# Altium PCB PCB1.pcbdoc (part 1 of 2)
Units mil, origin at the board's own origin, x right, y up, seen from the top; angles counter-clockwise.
Board outline 2401.6 x 2401.6 mil, 2 copper layers (Top Layer, Bottom Layer), stack 62.2 mil thick; 60 components, 46 nets, 313 pads, 160 vias.
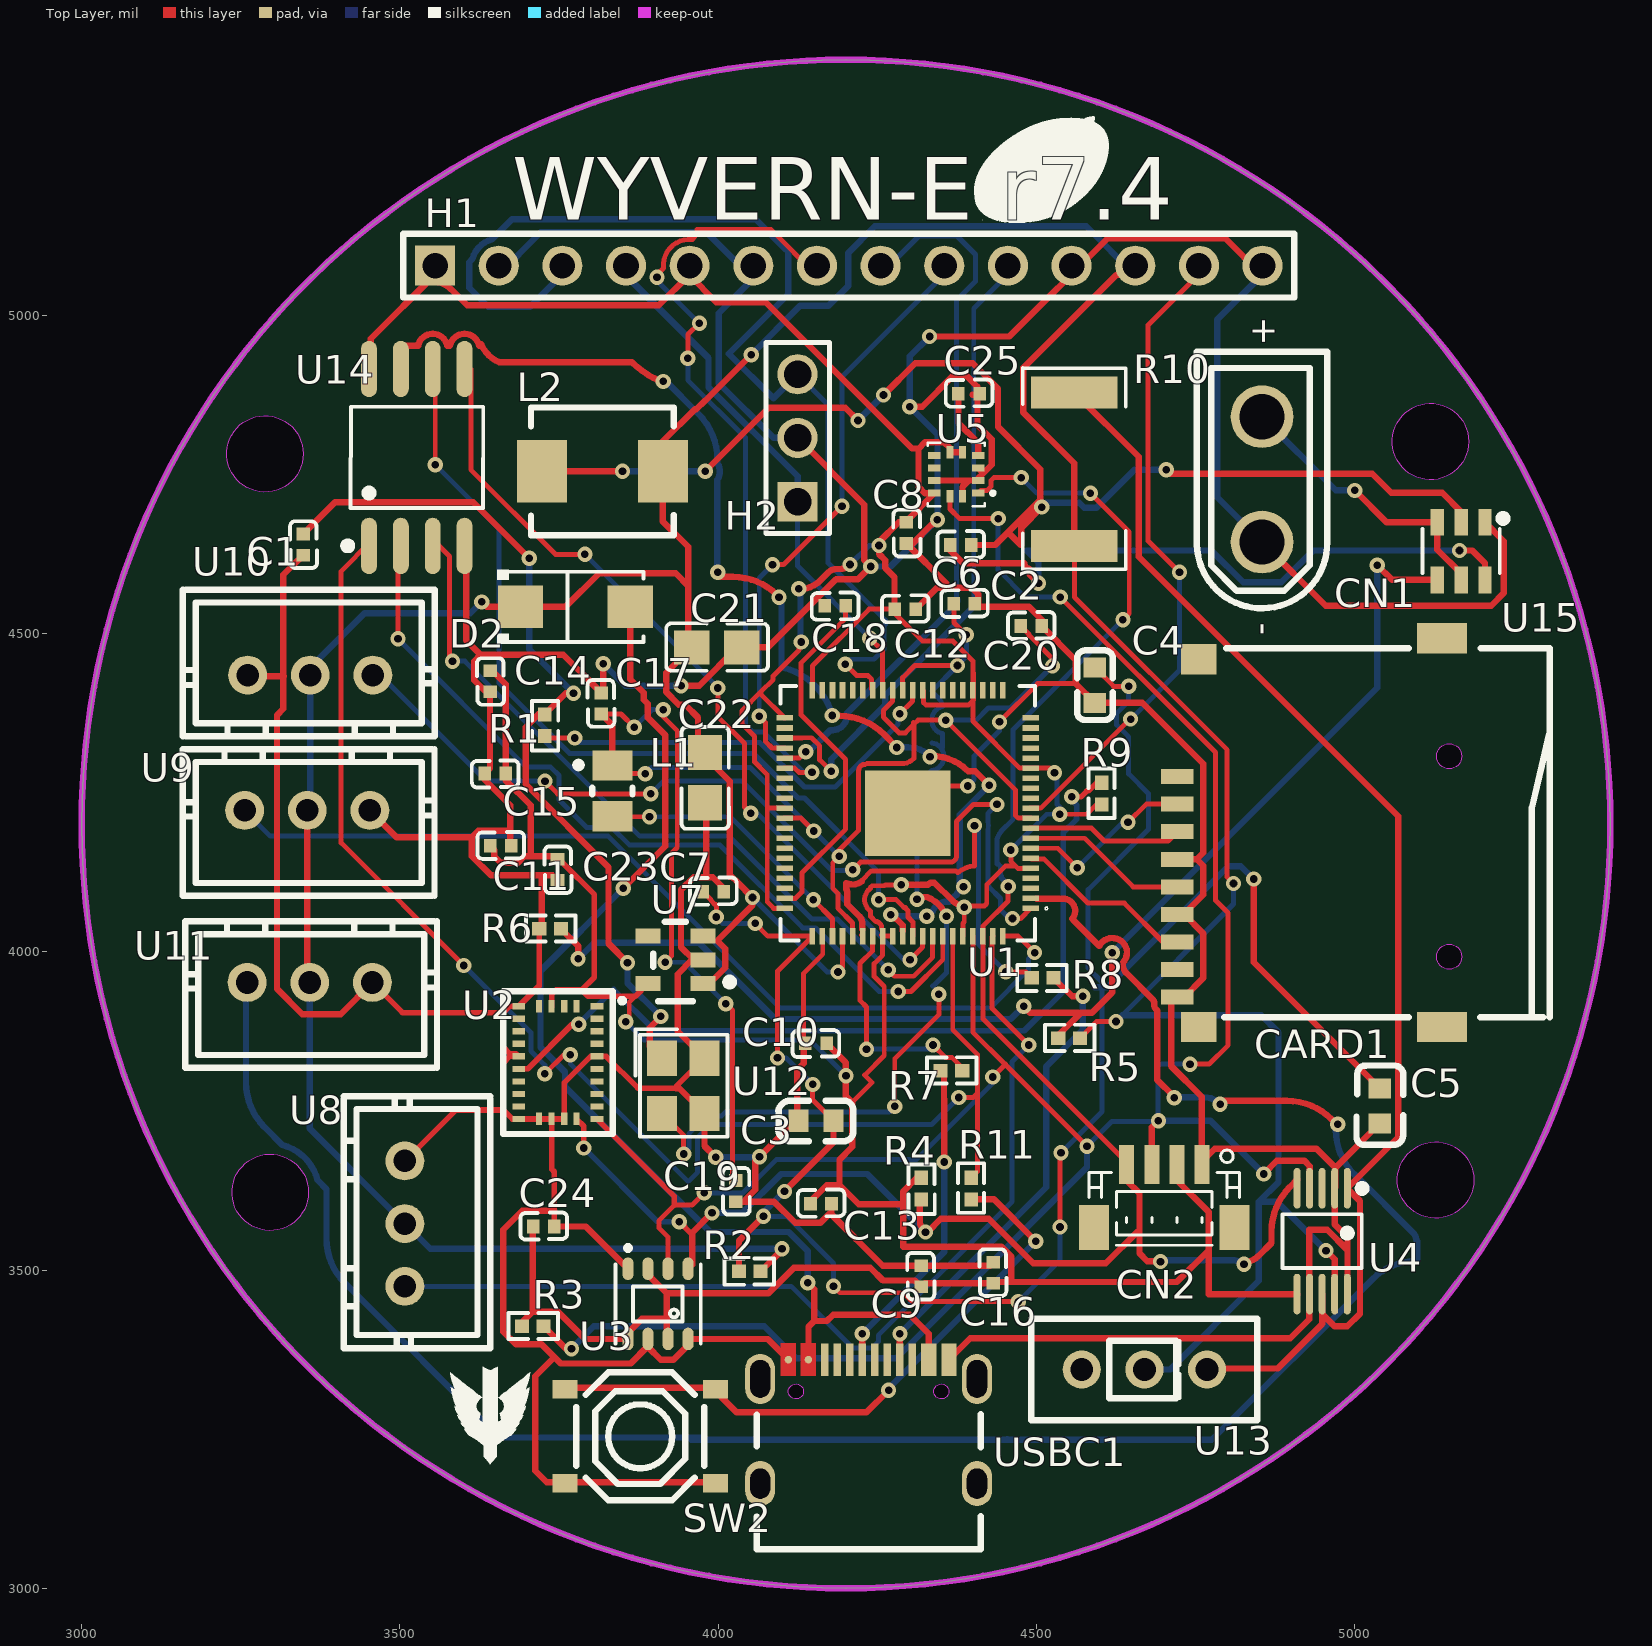
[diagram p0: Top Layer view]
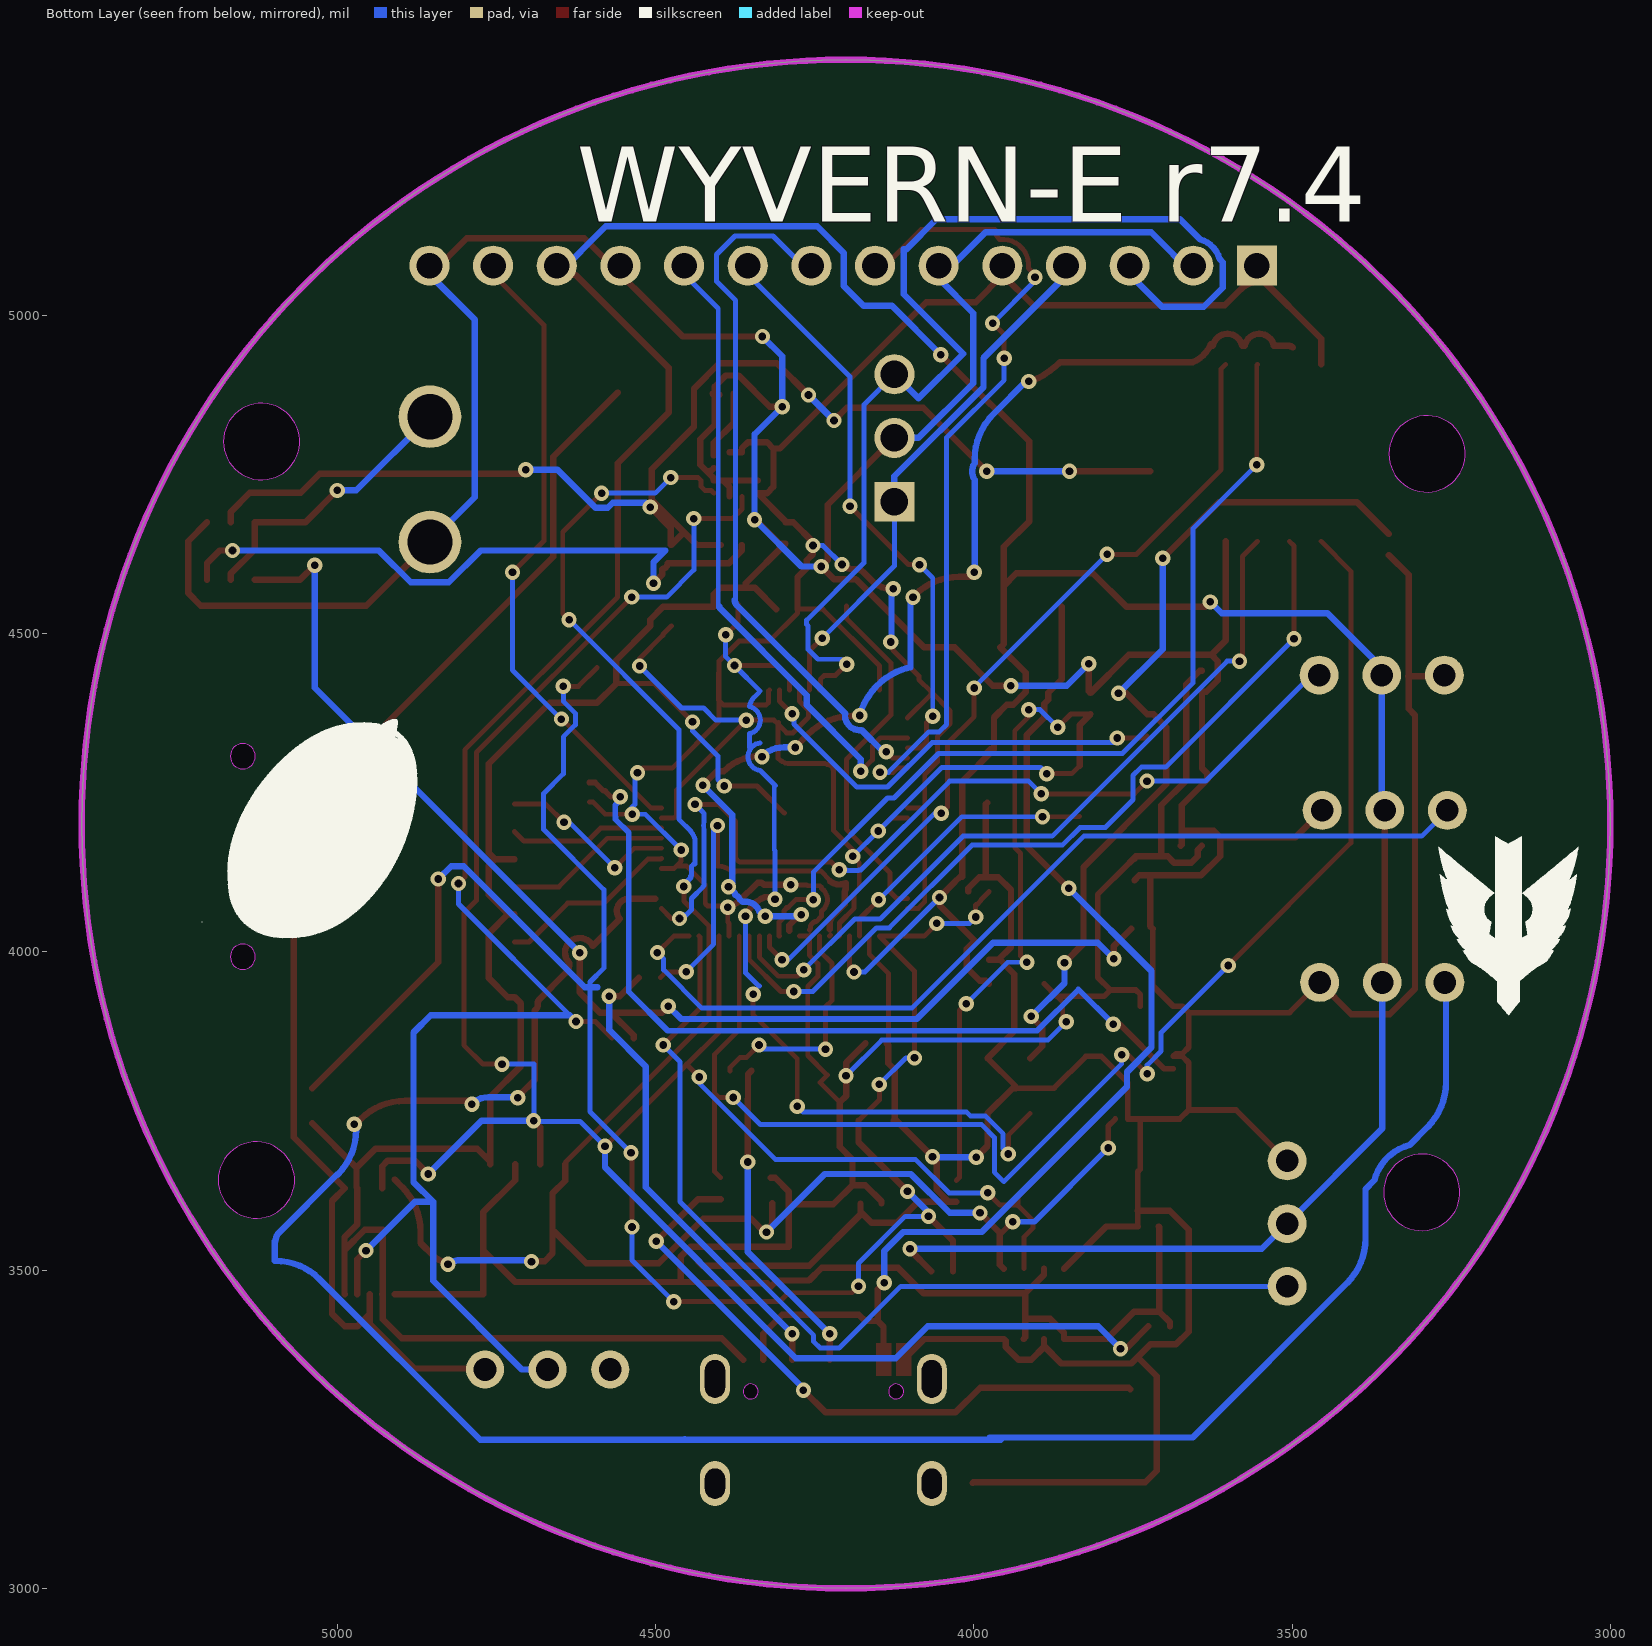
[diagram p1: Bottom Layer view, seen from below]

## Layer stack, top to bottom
Top Solder Mask Layer: solder mask 0.4, Dk 3.3
Top Layer: signal copper 1.4
Dielectric1: surface 59.4, FR4, Dk 4.5
Bottom Layer: signal copper 1.4
Bottom Solder Mask Layer: solder mask 0.4, Dk 3.3

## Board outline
5401.6,4200.8 ccw(c4200.8,4200.8) 3000,4200.8 ccw(c4200.8,4200.8)
cut-out: 3348,4782.3 3347.6,4775.5 3346.5,4768.7 3344.5,4762.1 3341.9,4755.8 3338.5,4749.8 3334.5,4744.3 3329.8,4739.3 3324.7,4734.8 3319,4730.9 3312.9,4727.7 3306.5,4725.2 3299.9,4723.5 3293.1,4722.5 3286.3,4722.3 3279.4,4722.9 3272.7,4724.2 3266.2,4726.4 3260,4729.2 3254.1,4732.7 3248.7,4736.9 3243.8,4741.7 3239.4,4747 3235.7,4752.8 3232.7,4758.9 3230.4,4765.4 3228.8,4772.1 3228,4778.9 3228,4785.7 3228.8,4792.5 3230.4,4799.2 3232.7,4805.7 3235.7,4811.8 3239.4,4817.6 3243.8,4822.9 3248.7,4827.7 3254.1,4831.9 3260,4835.4 3266.2,4838.3 3272.7,4840.4 3279.4,4841.7 3286.3,4842.3 3293.1,4842.1 3299.9,4841.2 3306.5,4839.4 3312.9,4836.9 3319,4833.7 3324.7,4829.9 3329.8,4825.4 3334.5,4820.3 3338.5,4814.8 3341.9,4808.8 3344.5,4802.5 3346.5,4795.9 3347.6,4789.2
cut-out: 5179,4801.7 5178.6,4794.8 5177.4,4788.1 5175.5,4781.5 5172.8,4775.2 5169.4,4769.2 5165.4,4763.7 5160.8,4758.6 5155.6,4754.1 5149.9,4750.2 5143.9,4747 5137.5,4744.6 5130.9,4742.8 5124.1,4741.8 5117.2,4741.6 5110.4,4742.2 5103.7,4743.6 5097.2,4745.7 5090.9,4748.6 5085,4752.1 5079.6,4756.3 5074.7,4761.1 5070.4,4766.4 5066.7,4772.1 5063.6,4778.3 5061.3,4784.7 5059.8,4791.4 5059,4798.2 5059,4805.1 5059.8,4811.9 5061.3,4818.6 5063.6,4825 5066.7,4831.2 5070.4,4837 5074.7,4842.3 5079.6,4847 5085,4851.2 5090.9,4854.8 5097.2,4857.6 5103.7,4859.7 5110.4,4861.1 5117.2,4861.7 5124.1,4861.5 5130.9,4860.5 5137.5,4858.8 5143.9,4856.3 5149.9,4853.1 5155.6,4849.2 5160.8,4844.7 5165.4,4839.7 5169.4,4834.1 5172.8,4828.2 5175.5,4821.8 5177.4,4815.3 5178.6,4808.5
cut-out: 3356.3,3622.1 3355.9,3615.3 3354.7,3608.5 3352.8,3601.9 3350.1,3595.6 3346.7,3589.7 3342.7,3584.1 3338.1,3579.1 3332.9,3574.6 3327.2,3570.7 3321.2,3567.5 3314.8,3565 3308.1,3563.3 3301.4,3562.3 3294.5,3562.1 3287.7,3562.7 3281,3564.1 3274.4,3566.2 3268.2,3569 3262.3,3572.6 3256.9,3576.7 3252,3581.5 3247.6,3586.8 3243.9,3592.6 3240.9,3598.7 3238.6,3605.2 3237.1,3611.9 3236.3,3618.7 3236.3,3625.5 3237.1,3632.4 3238.6,3639 3240.9,3645.5 3243.9,3651.6 3247.6,3657.4 3252,3662.7 3256.9,3667.5 3262.3,3671.7 3268.2,3675.2 3274.4,3678.1 3281,3680.2 3287.7,3681.6 3294.5,3682.1 3301.4,3681.9 3308.1,3681 3314.8,3679.2 3321.2,3676.7 3327.2,3673.5 3332.9,3669.7 3338.1,3665.2 3342.7,3660.1 3346.7,3654.6 3350.1,3648.6 3352.8,3642.3 3354.7,3635.7 3355.9,3629
cut-out: 5187.2,3641.5 5186.8,3634.6 5185.6,3627.9 5183.7,3621.3 5181,3615 5177.7,3609 5173.6,3603.5 5169,3598.4 5163.8,3593.9 5158.2,3590.1 5152.1,3586.9 5145.7,3584.4 5139.1,3582.6 5132.3,3581.6 5125.4,3581.5 5118.6,3582 5111.9,3583.4 5105.4,3585.5 5099.1,3588.4 5093.3,3591.9 5087.8,3596.1 5082.9,3600.9 5078.6,3606.2 5074.9,3611.9 5071.9,3618.1 5069.6,3624.6 5068,3631.2 5067.2,3638 5067.2,3644.9 5068,3651.7 5069.6,3658.4 5071.9,3664.8 5074.9,3671 5078.6,3676.8 5082.9,3682.1 5087.8,3686.8 5093.3,3691 5099.1,3694.6 5105.4,3697.4 5111.9,3699.5 5118.6,3700.9 5125.4,3701.5 5132.3,3701.3 5139.1,3700.3 5145.7,3698.6 5152.1,3696.1 5158.2,3692.9 5163.8,3689 5169,3684.5 5173.6,3679.5 5177.7,3673.9 5181,3668 5183.7,3661.6 5185.6,3655.1 5186.8,3648.3

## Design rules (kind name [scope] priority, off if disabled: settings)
BoardOutlineClearance safeClearance [All] p0: genericclearance=10 ignorepadtopadclearanceinfootprint=FALSE except(0: Arc-SplitContinuation Track-SplitContinuation SMDPad-SplitContinuation THPad-SplitContinuation Via-SplitContinuation Fill-SplitContinuation Poly-SplitContinuation Region-SplitContinuation Text-SplitContinuation)
BoardOutlineClearance otherClearance [All] p0: genericclearance=10 ignorepadtopadclearanceinfootprint=FALSE except(0: Arc-SplitContinuation Track-SplitContinuation SMDPad-SplitContinuation THPad-SplitContinuation Via-SplitContinuation Fill-SplitContinuation Poly-SplitContinuation Region-SplitContinuation Text-SplitContinuation)
Clearance safeClearance [All] p1: gap=7 ignorepadtopadclearanceinfootprint=FALSE
Clearance otherClearance [All] p1: gap=7 ignorepadtopadclearanceinfootprint=FALSE
DiffPairsRouting differentialPair [All] p1: maxuncoupledlength=10 minlimit=6 maxlimit=Infinity mostfreqgap=6 toplayer_minwidth=5 toplayer_prefwidth=10 toplayer_maxwidth=100 bottomlayer_minwidth=5 bottomlayer_prefwidth=10 bottomlayer_maxwidth=100
PasteMaskExpansion pasteMaskExpansion [All] p1: expansion=0
PlaneConnect innerPlane [All] p1: planeconnectstyle=Relief reliefexpansion=20 reliefentries=4 reliefconductorwidth=10 reliefairgap=10
PolygonConnect copperRegion [All] p1: connectstyle=Relief reliefentries=4 reliefconductorwidth=10 polygonreliefangle="90 Angle" airgapwidth=10
RoutingVias viaSize [All] p1: viastyle="Through Hole" holewidth=12.0078 minholewidth=11.811 maxholewidth=236.2204 width=12.0078 minwidth=11.811 maxwidth=236.2204
SolderMaskExpansion solderMaskExpansion [IsVia] p1: useseparateexpansions=TRUE expansion=-1000 expansionbottom=-1000
SolderMaskExpansion solderMaskExpansion [All] p2: useseparateexpansions=TRUE expansion=0.9843 expansionbottom=2.0079
Width trackWidth [All] p1: maxlimit=100 minlimit=5 preferedwidth=10

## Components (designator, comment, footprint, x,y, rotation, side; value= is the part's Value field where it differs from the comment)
C1 "15pF" C0402#1 3347.9,4639.8 r270 top
C2 "15pF" C0402#1 4386.9,4546.8 r0 top
C3 "4.7uF" C0603#1 4153.6,3734.4 r180 top
C4 "4.7uF" C0603#2 4591.9,4418.8 r270 top
C5 "4.7uF" C0603#2 5039.4,3758 r270 top
C6 "100nF" C0402#2 4380.8,4639.1 r0 top
C7 "100nF" C0402#2 3992.3,4094.7 r0 top
C8 "100nF" C0402#2 4295.8,4658.1 r270 top
C9 "100nF" C0402#1 4319,3490.3 r90 top
C10 "100nF" C0402#1 4153.6,3856.4 r180 top
C11 "100nF" C0402#2 3658.2,4166.5 r0 top
C12 "100nF" C0402#1 4293.7,4538.4 r0 top
C13 "100nF" C0402#3 4161.5,3604.4 r0 top
C14 "100nF" C0402#2 3641.6,4424.9 r270 top
C15 "100nF" C0402#2 3649.7,4280.1 r180 top
C16 "100nF" C0402#1 4432.4,3495.9 r90 top
C17 "100nF" C0402#3 3816.6,4390.1 r90 top
C18 "100nF" C0402#1 4183.7,4543.7 r180 top
C19 "100nF" C0402#1 4027.6,3624.1 r270 top
C20 "100nF" C0402#2 4491.7,4511.9 r0 top
C21 "22uF" C0805#1 3997.7,4478.2 r0 top
C22 "22uF" C0805#2 3979.1,4273.8 r270 top
C23 "100nF" C0402#2 3747.6,4129 r270 top
C24 "100nF" C0402#2 3725.8,3568.5 r0 top
C25 "100nF" C0402#1 4394.1,4877 r0 top
CARD1 "TF-01A" TF-SMD_TF-01A 4929.2,4187.1 r90 top
CN1 "XT30UPB-M" CONN-TH_XT30UPB-M 4854.4,4742.2 r90 top
CN2 "BM04B-SRSS-TB(LF)(SN)" CONN-SMD_BM04B-SRSS-TB 4700.9,3616.3 r180 top
D2 "SS14" SMA_L4.4-W2.6-LS5.0-RD 3775.5,4541.9 r0 top
H1 "2011-1X14G00SB" HDR-TH_14P-P2.54-V-M_4 4205.2,5078 r0 top
H2 "2.54-1*3P针" HDR-TH_3P-P2.54-V-M-1 4124.8,4807.4 r90 top
L1 "3.3uH" IND-SMD_L2.0-W1.6_AOTA-B201610S3R3-101-T 3833.8,4253 r90 top
L2 "2.2uH" IND-SMD_L5.7-W5.1 3818.1,4754.8 r0 top
R1 "1kΩ" R0402#1 3727.6,4356 r90 top
R2 "33Ω" R0402#1 4049.7,3498.2 r0 top
R3 "10kΩ" R0402#1 3708.7,3411.5 r180 top
R4 "10kΩ" R0402#1 4319,3628.1 r90 top
R5 "56kΩ" R0402#2 4551.3,3864.3 r180 top
R6 "10.2kΩ" R0402#1 3735.8,4036.2 r180 top
R7 "27Ω" R0402#1 4366.2,3813.1 r180 top
R8 "27Ω" R0402#2 4509.5,3959.4 r0 top
R9 "10kΩ" R0402#1 4602.7,4248.4 r270 top
R10 "10mΩ" R2512 4559.5,4758.1 r270 top
R11 "1kΩ" R0402#2 4397.7,3628.1 r270 top
SW2 "TS-1187A-B-A-B" SW-SMD_4P-L5.1-W5.1-P3.70-LS6.5-TL_H1.5 3877.5,3238.8 r0 top
U1 "RP2350B" QFN-80_L10.0-W10.0-P0.40-TL-EP3.4 4297.7,4217.8 r180 top
U2 "BNO055" LGA-28_L5.2-W3.8-P0.50-BL 3748.1,3825.9 r180 top
U3 "BME680" LGA-8_L3.0-W3.0-P0.80-TR 3905.6,3447 r90 top
U4 "INA226AIDGSR" MSOP-10_L3.0-W3.0-P0.50-LS5.0-BL 4948.9,3545.4 r180 top
U5 "LIS3MDLTR" LGA-12_L2.0-W2.0-P0.50-BL 4374.1,4750.1 r90 top
U7 "AP2112K-3.3TRG1" SOT-23-5_L2.9-W1.6-P0.95-LS2.8-BR 3932.9,3987.4 r0 top
U8 "B3B-XH-A(LF)(SN)" CONN-TH_3P-P2.50_A2501WV2-3P#1 3507.8,3573 r90 top
U9 "B3B-XH-A(LF)(SN)" CONN-TH_3P-P2.50_A2501WV2-3P#2 3354.4,4222.1 r0 top
U10 "B3B-XH-A(LF)(SN)" CONN-TH_3P-P2.50_A2501WV2-3P#2 3359.1,4434.8 r180 top
U11 "B3B-XH-A(LF)(SN)" CONN-TH_3P-P2.50_A2501WV2-3P#3 3358.3,3951.8 r0 top
U12 "12MHz" CRYSTAL-SMD_4P-L3.2-W2.5-BL 3945,3789.5 r270 top
U13 "SS-12D00-G3" SW-TH_3P-L8.8-W3.9-P2.50_SS12D00G3 4669.6,3343.8 r180 top
U14 "W25Q32JVSSIQ" SOIC-8_L5.3-W5.3-P1.27-LS8.0-BL 3526.5,4776.7 r0 top
U15 "TPS564201DDCR" SOT-23-6_L2.9-W1.6-P0.95-LS2.8-BL 5167.3,4629.6 r180 top
USBC1 "TYPE-C-31-M-12" USB-C_SMD-TYPE-C-31-M-12_1 4236.3,3261.9 r0 top

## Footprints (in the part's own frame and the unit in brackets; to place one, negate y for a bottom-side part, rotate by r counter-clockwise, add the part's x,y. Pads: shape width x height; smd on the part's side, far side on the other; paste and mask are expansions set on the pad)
C0402#1 [mil]
  rect 19.7x21.3 smd paste+0 mask+0: 1(-16.6,0) 2(16.5,0)
  silkscreen extent -36,-21 37,22
C0402#2 [mil]
  rect 19.7x21.3 smd paste+0 mask+0: 1(-16.5,0) 2(16.6,0)
  silkscreen extent -36,-21 37,22
C0402#3 [mil]
  rect 19.7x21.3 smd paste+0 mask+0: 1(-16.5,0) 2(16.5,0)
  silkscreen extent -36,-21 37,22
C0603#1 [mil]
  rect 31.5x35.4 smd: 1(-27.6,0) 2(27.5,0)
  silkscreen extent -59,-32 59,32
C0603#2 [mil]
  rect 31.5x35.4 smd paste+0 mask+0: 1(-27.6,0) 2(27.6,0)
  silkscreen extent -55,-28 55,28
C0805#1 [mil]
  rect 55.5x53.1 smd paste+0 mask+0: 1(-39.4,0) 2(39.4,0)
  silkscreen extent -79,-37 80,38
C0805#2 [mil]
  rect 55.5x53.1 smd paste-3937 mask+2: 1(-39.3,0) 2(39.4,0)
  silkscreen extent -79,-37 81,38
CONN-SMD_BM04B-SRSS-TB [mil]
  rect 47.2x70.9 smd: 0(-110.2,49.7) 0(110.3,49.7)
  rect 23.6x61 smd: 1(-59,-49.7) 2(-19.7,-49.7) 3(19.7,-49.7) 4(59.1,-49.7)
  silkscreen extent -118,-72 118,77
CONN-TH_3P-P2.50_A2501WV2-3P#1 [mil]
  round 61 hole 35.4: 1(-98.5,0) 2(0,0) 3(98.4,0)
  silkscreen extent -196,-134 200,96
CONN-TH_3P-P2.50_A2501WV2-3P#2 [mil]
  round 61 hole 35.4: 1(-98.4,0) 2(0,0) 3(98.4,0)
  silkscreen extent -196,-134 200,96
CONN-TH_3P-P2.50_A2501WV2-3P#3 [mil]
  round 61 hole 35.4: 1(-98.4,0) 2(0.1,0) 3(98.5,0)
  silkscreen extent -196,-134 200,96
CONN-TH_XT30UPB-M [mil]
  round 98.4 hole 70.9: 1(-98.4,0) 2(98.5,0)
  silkscreen extent -202,-102 201,102
CRYSTAL-SMD_4P-L3.2-W2.5-BL [mil]
  rect 55.1x47.2 smd paste+0 mask+0: 1(-43.3,-33.5) 2(43.3,-33.5) 3(43.3,33.4) 4(-43.3,33.4)
  silkscreen extent -89,-75 80,70
HDR-TH_3P-P2.54-V-M-1 [mil]
  rect 62x63 hole 43.3: 1(-100,0)
  round 63 hole 43.3: 2(0,0) 3(100,0)
  silkscreen extent -150,-50 150,50
HDR-TH_14P-P2.54-V-M_4 [mil]
  rect 63x63 hole 40.2: 1(-650,0)
  round 63 hole 40.2: 2(-550,0) 3(-450,0) 4(-350,0) 5(-250,0) 6(-150,0) 7(-50,0) 8(50,0) 9(150,0) 10(250,0) 11(350,0) 12(450,0) 13(550,0) 14(650,0)
  silkscreen extent -700,-50 700,50
IND-SMD_L2.0-W1.6_AOTA-B201610S3R3-101-T [mil]
  rect 47.2x63 smd paste+0 mask+0: 1(-40,0) 2(39.4,0)
  silkscreen extent -6,-32 46,58
IND-SMD_L5.7-W5.1 [mil]
  rect 78.7x98.4 smd paste+0 mask+2: 1(-95,0) 2(95,0)
  silkscreen extent -112,-100 112,100
LGA-8_L3.0-W3.0-P0.80-TR [mil]
  oval 35.4x17.6 smd paste+0 mask+0: 1(55.1,47.2) 2(55.1,15.8) 3(55.1,-15.7) 4(55.1,-47.2) 5(-55.2,-47.2) 6(-55.2,-15.7) 7(-55.2,15.8) 8(-55.2,47.2)
  silkscreen extent -62,-67 92,67
LGA-12_L2.0-W2.0-P0.50-BL [mil]
  rect 11x19.7 smd: 1(-29.5,-34.4) 2(-9.8,-34.4) 3(9.9,-34.4) 4(29.5,-34.4) 7(29.5,34.5) 8(9.9,34.5) 9(-9.8,34.5) 10(-29.5,34.5)
  rect 19.7x11 smd: 5(34.5,-9.8) 6(34.5,9.8) 11(-34.4,9.8) 12(-34.4,-9.8)
  silkscreen extent -50,-60 50,45
LGA-28_L5.2-W3.8-P0.50-BL [mil]
  rect 19.7x9.8 smd: 1(-61.5,-88.6) 6(61.5,-88.6) 7(61.5,-68.9) 8(61.5,-49.2) 9(61.5,-29.6) 10(61.5,-9.9) 11(61.5,9.8) 12(61.5,29.5) 13(61.5,49.2) 14(61.5,68.9) 15(61.5,88.5) 20(-61.5,88.5) 21(-61.5,68.9) 22(-61.5,49.2) 23(-61.5,29.5) 24(-61.5,9.8) 25(-61.5,-9.9) 26(-61.5,-29.6) 27(-61.5,-49.2) 28(-61.5,-68.9)
  rect 9.8x19.7 smd: 2(-29.5,-88.6) 3(-9.9,-88.6) 4(9.8,-88.6) 5(29.5,-88.6) 16(29.5,88.5) 17(9.8,88.5) 18(-9.9,88.5) 19(-29.5,88.5)
  silkscreen extent -105,-112 86,112
MSOP-10_L3.0-W3.0-P0.50-LS5.0-BL [mil]
  oval 11x63.8 smd paste+0 mask+0: 1(-39.4,-83.1) 2(-19.7,-83.1) 3(0,-83.1) 4(19.7,-83.1) 5(39.4,-83.1) 6(39.4,83.1) 7(19.7,83.1) 8(0,83.1) 9(-19.7,83.1) 10(-39.4,83.1)
  silkscreen extent -69,-89 62,42
QFN-80_L10.0-W10.0-P0.40-TL-EP3.4 [mil]
  rect 26.2x8.7 smd: 1(-193.2,149.6) 2(-193.2,133.9) 3(-193.2,118.1) 4(-193.2,102.4) 5(-193.2,86.6) 6(-193.2,70.9) 7(-193.2,55.1) 8(-193.2,39.4) 9(-193.2,23.6) 10(-193.2,7.9) 11(-193.2,-7.8) 12(-193.2,-23.6) 13(-193.2,-39.3) 14(-193.2,-55.1) 15(-193.2,-70.8) 16(-193.2,-86.6) 17(-193.2,-102.3) 18(-193.2,-118.1) 19(-193.2,-133.8) 20(-193.2,-149.6) 41(193.2,-149.6) 42(193.2,-133.8) 43(193.2,-118.1) 44(193.2,-102.3) 45(193.2,-86.6) 46(193.2,-70.8) 47(193.2,-55.1) 48(193.2,-39.3) 49(193.2,-23.6) 50(193.2,-7.8) 51(193.2,7.9) 52(193.2,23.6) 53(193.2,39.4) 54(193.2,55.1) 55(193.2,70.9) 56(193.2,86.6) 57(193.2,102.4) 58(193.2,118.1) 59(193.2,133.9) 60(193.2,149.6)
  rect 8.7x26.2 smd: 21(-149.6,-193.2) 22(-133.8,-193.2) 23(-118.1,-193.2) 24(-102.3,-193.2) 25(-86.6,-193.2) 26(-70.8,-193.2) 27(-55.1,-193.2) 28(-39.3,-193.2) 29(-23.6,-193.2) 30(-7.8,-193.2) 31(7.9,-193.2) 32(23.6,-193.2) 33(39.4,-193.2) 34(55.1,-193.2) 35(70.9,-193.2) 36(86.6,-193.2) 37(102.4,-193.2) 38(118.1,-193.2) 39(133.9,-193.2) 40(149.6,-193.2) 61(149.6,193.2) 62(133.9,193.2) 63(118.1,193.2) 64(102.4,193.2) 65(86.6,193.2) 66(70.9,193.2) 67(55.1,193.2) 68(39.4,193.2) 69(23.6,193.2) 70(7.9,193.2) 71(-7.8,193.2) 72(-23.6,193.2) 73(-39.3,193.2) 74(-55.1,193.2) 75(-70.8,193.2) 76(-86.6,193.2) 77(-102.3,193.2) 78(-118.1,193.2) 79(-133.8,193.2) 80(-149.6,193.2)
  rect 133.9x133.9 smd: 81(0,0)
  silkscreen extent -220,-200 200,200
R0402#1 [mil]
  rect 22.3x21.3 smd paste-3937 mask+0: 1(-17.1,0) 2(17,0)
  silkscreen extent -40,-21 38,20
R0402#2 [mil]
  rect 22.3x21.3 smd paste-3937 mask+0: 1(-17,0) 2(17.1,0)
  silkscreen extent -40,-21 38,20
R2512 [mil]
  rect 50.5x136.1 smd paste-3937 mask+2: 1(-120.7,0) 2(120.8,0)
  silkscreen extent -159,-81 158,81
SMA_L4.4-W2.6-LS5.0-RD [mil]
  rect 70.9x66.9 smd: 1(-86.3,0) 2(86.3,0)
  silkscreen extent -122,-58 107,58
SOIC-8_L5.3-W5.3-P1.27-LS8.0-BL [mil]
  oval 24.8x88.6 smd: 1(-75,-139) 2(-25,-139) 3(25,-139) 4(75,-139) 5(75,139) 6(25,139) 7(-25,139) 8(-75,139)
  silkscreen extent -115,-145 104,80
SOT-23-5_L2.9-W1.6-P0.95-LS2.8-BR [mil]
  rect 39.4x23.6 smd paste+0 mask+2: 1(43.3,-37.4) 2(43.3,0) 3(43.3,37.4) 4(-43.3,37.4) 5(-43.3,-37.4)
  silkscreen extent -35,-65 91,60
SOT-23-6_L2.9-W1.6-P0.95-LS2.8-BL [mil]
  rect 20.9x42.2 smd: 1(-37.4,-45.3) 2(0,-45.3) 3(37.4,-45.3) 4(37.4,45.2) 5(0,45.2) 6(-37.4,45.2)
  silkscreen extent -72,-57 61,35
SW-SMD_4P-L5.1-W5.1-P3.70-LS6.5-TL_H1.5 [mil]
  rect 39.4x29.5 smd: 1(-118.1,73.9) 2(118.1,73.9) 3(-118.1,-73.8) 4(118.1,-73.8)
  silkscreen extent -100,-100 100,100
SW-TH_3P-L8.8-W3.9-P2.50_SS12D00G3 [mil]
  round 60 hole 36 paste+0 mask+2: 1(-98.4,0) 2(0,0) 3(98.4,0)
  silkscreen extent -178,-80 178,80
TF-SMD_TF-01A [mil]
  rect 23.6x51.2 smd: 1(88.2,207.7) 2(44.9,207.7) 3(1.6,207.7) 4(-41.7,207.7) 5(-85,207.7) 6(-128.3,207.7) 7(-171.6,207.7) 8(-214.9,207.7) 9(-258.2,207.7)
  rect 47.2x55.1 smd: 10(-305.5,174.2) 13(272.5,174.2)
  rect 47.2x78.7 smd paste+0 mask+0: 11(-305.5,-207.7) 12(305.5,-207.7)
  Board Outline Layer lines w0.1: -194.9,-199.5 -198.7,-199.8 -202.4,-201 -205.8,-202.8 -208.8,-205.2 -211.2,-208.2 -213,-211.6 -214.2,-215.3 -214.5,-219.1 -214.2,-223 -213,-226.7 -211.2,-230.1 -208.8,-233.1 -205.8,-235.5 -202.4,-237.3 -198.7,-238.5 -194.9,-238.8 -191,-238.5 -187.3,-237.3 -183.9,-235.5 -180.9,-233.1 -178.5,-230.1 -176.7,-226.7 -175.5,-223 -175.2,-219.1 -175.5,-215.3 -176.7,-211.6 -178.5,-208.2 -180.9,-205.2 -183.9,-202.8 -187.3,-201 -191,-199.8 -194.9,-199.5 ; 120.1,-199.5 116.3,-199.8 112.6,-201 109.2,-202.8 106.2,-205.2 103.7,-208.2 101.9,-211.6 100.8,-215.3 100.4,-219.1 100.8,-223 101.9,-226.7 103.7,-230.1 106.2,-233.1 109.2,-235.5 112.6,-237.3 116.3,-238.5 120.1,-238.8 123.9,-238.5 127.6,-237.3 131,-235.5 134,-233.1 136.5,-230.1 138.3,-226.7 139.4,-223 139.8,-219.1 139.4,-215.3 138.3,-211.6 136.5,-208.2 134,-205.2 131,-202.8 127.6,-201 123.9,-199.8 120.1,-199.5
  Board Outline Layer region: -175.2,-219.1 -175.5,-223 -176.7,-226.7 -178.5,-230.1 -180.9,-233.1 -183.9,-235.5 -187.3,-237.3 -191,-238.5 -194.9,-238.8 -198.7,-238.5 -202.4,-237.3 -205.8,-235.5 -208.8,-233.1 -211.2,-230.1 -213,-226.7 -214.2,-223 -214.5,-219.1 -214.2,-215.3 -213,-211.6 -211.2,-208.2 -208.8,-205.2 -205.8,-202.8 -202.4,-201 -198.7,-199.8 -194.9,-199.5 -191,-199.8 -187.3,-201 -183.9,-202.8 -180.9,-205.2 -178.5,-208.2 -176.7,-211.6 -175.5,-215.3
  Board Outline Layer region: -175.2,-219.1 -175.5,-223 -176.7,-226.7 -178.5,-230.1 -180.9,-233.1 -183.9,-235.5 -187.3,-237.3 -191,-238.5 -194.9,-238.8 -198.7,-238.5 -202.4,-237.3 -205.8,-235.5 -208.8,-233.1 -211.2,-230.1 -213,-226.7 -214.2,-223 -214.5,-219.1 -214.2,-215.3 -213,-211.6 -211.2,-208.2 -208.8,-205.2 -205.8,-202.8 -202.4,-201 -198.7,-199.8 -194.9,-199.5 -191,-199.8 -187.3,-201 -183.9,-202.8 -180.9,-205.2 -178.5,-208.2 -176.7,-211.6 -175.5,-215.3
  Board Outline Layer region: 139.8,-219.1 139.4,-223 138.3,-226.7 136.5,-230.1 134,-233.1 131,-235.5 127.6,-237.3 123.9,-238.5 120.1,-238.8 116.3,-238.5 112.6,-237.3 109.2,-235.5 106.2,-233.1 103.7,-230.1 101.9,-226.7 100.8,-223 100.4,-219.1 100.8,-215.3 101.9,-211.6 103.7,-208.2 106.2,-205.2 109.2,-202.8 112.6,-201 116.3,-199.8 120.1,-199.5 123.9,-199.8 127.6,-201 131,-202.8 134,-205.2 136.5,-208.2 138.3,-211.6 139.4,-215.3
  Board Outline Layer region: 139.8,-219.1 139.4,-223 138.3,-226.7 136.5,-230.1 134,-233.1 131,-235.5 127.6,-237.3 123.9,-238.5 120.1,-238.8 116.3,-238.5 112.6,-237.3 109.2,-235.5 106.2,-233.1 103.7,-230.1 101.9,-226.7 100.8,-223 100.4,-219.1 100.8,-215.3 101.9,-211.6 103.7,-208.2 106.2,-205.2 109.2,-202.8 112.6,-201 116.3,-199.8 120.1,-199.5 123.9,-199.8 127.6,-201 131,-202.8 134,-205.2 136.5,-208.2 138.3,-211.6 139.4,-215.3
  Multi-Layer board cut-out: -175.2,-219.1 -175.5,-223 -176.7,-226.7 -178.5,-230.1 -180.9,-233.1 -183.9,-235.5 -187.3,-237.3 -191,-238.5 -194.9,-238.8 -198.7,-238.5 -202.4,-237.3 -205.8,-235.5 -208.8,-233.1 -211.2,-230.1 -213,-226.7 -214.2,-223 -214.5,-219.1 -214.2,-215.3 -213,-211.6 -211.2,-208.2 -208.8,-205.2 -205.8,-202.8 -202.4,-201 -198.7,-199.8 -194.9,-199.5 -191,-199.8 -187.3,-201 -183.9,-202.8 -180.9,-205.2 -178.5,-208.2 -176.7,-211.6 -175.5,-215.3
  Multi-Layer board cut-out: 139.8,-219.1 139.4,-223 138.3,-226.7 136.5,-230.1 134,-233.1 131,-235.5 127.6,-237.3 123.9,-238.5 120.1,-238.8 116.3,-238.5 112.6,-237.3 109.2,-235.5 106.2,-233.1 103.7,-230.1 101.9,-226.7 100.8,-223 100.4,-219.1 100.8,-215.3 101.9,-211.6 103.7,-208.2 106.2,-205.2 109.2,-202.8 112.6,-201 116.3,-199.8 120.1,-199.5 123.9,-199.8 127.6,-201 131,-202.8 134,-205.2 136.5,-208.2 138.3,-211.6 139.4,-215.3
  silkscreen extent -290,-377 290,134
USB-C_SMD-TYPE-C-31-M-12_1 [mil]
  oval 47.2x78.7 hole 31.5 slot 59.1 at 90 deg paste+0 mask+2: 1(170.3,67.2) 4(-170.3,67.2)
  oval 47.2x70.9 hole 31.5 slot 47.2 at 90 deg paste+0 mask+2: 2(170.3,-97.4) 3(-170.3,-97.4)
  round 11.8 smd: A1B12(-126,97.4) A4B9(-94.5,97.4)
  rect 11.8x51.2 smd paste-3937 mask+0: A5(-49.2,97.4) A6(-9.8,97.4) A7(9.8,97.4) A8(49.2,97.4) B5(68.9,97.4) B6(29.5,97.4) B7(-29.5,97.4) B8(-68.9,97.4)
  rect 23.6x51.2 smd paste-3937 mask+0: B1A12(126,97.4) B4A9(94.5,97.4)
  Top Layer region: -114.2,71.8 -126,71.8 -126,71.8 -137.8,71.8 -137.8,123 -126,123 -126,123 -114.2,123
  Top Layer region: -82.7,71.8 -94.5,71.8 -94.5,71.8 -106.3,71.8 -106.3,123 -94.5,123 -94.5,123 -82.7,123
  Board Outline Layer lines w0.1: -125.9,46 -125.2,43.1 -123.7,40.6 -121.7,38.4 -119.2,36.8 -116.4,35.9 -113.4,35.7 -110.5,36.3 -107.8,37.5 -105.6,39.4 -103.8,41.8 -102.7,44.6 -102.4,47.5 -102.7,50.4 -103.8,53.2 -105.6,55.6 -107.8,57.5 -110.5,58.7 -113.4,59.3 -116.4,59.1 -119.2,58.2 -121.7,56.6 -123.7,54.4 -125.2,51.8 -125.9,49 -125.9,46 ; 102.5,46 103.2,43.1 104.6,40.6 106.6,38.4 109.1,36.8 112,35.9 114.9,35.7 117.8,36.3 120.5,37.5 122.8,39.4 124.5,41.8 125.6,44.6 126,47.5 125.6,50.4 124.5,53.2 122.8,55.6 120.5,57.5 117.8,58.7 114.9,59.3 112,59.1 109.1,58.2 106.6,56.6 104.6,54.4 103.2,51.8 102.5,49 102.5,46
  Board Outline Layer region: -102.4,47.5 -102.7,44.6 -103.8,41.8 -105.6,39.4 -107.8,37.5 -110.5,36.3 -113.4,35.7 -116.4,35.9 -119.2,36.8 -121.7,38.4 -123.7,40.6 -125.2,43.1 -125.9,46 -125.9,49 -125.2,51.8 -123.7,54.4 -121.7,56.6 -119.2,58.2 -116.4,59.1 -113.4,59.3 -110.5,58.7 -107.8,57.5 -105.6,55.6 -103.8,53.2 -102.7,50.4
  Board Outline Layer region: -102.4,47.5 -102.7,44.6 -103.8,41.8 -105.6,39.4 -107.8,37.5 -110.5,36.3 -113.4,35.7 -116.4,35.9 -119.2,36.8 -121.7,38.4 -123.7,40.6 -125.2,43.1 -125.9,46 -125.9,49 -125.2,51.8 -123.7,54.4 -121.7,56.6 -119.2,58.2 -116.4,59.1 -113.4,59.3 -110.5,58.7 -107.8,57.5 -105.6,55.6 -103.8,53.2 -102.7,50.4
  Board Outline Layer region: 126,47.5 125.6,44.6 124.5,41.8 122.8,39.4 120.5,37.5 117.8,36.3 114.9,35.7 112,35.9 109.1,36.8 106.6,38.4 104.6,40.6 103.2,43.1 102.5,46 102.5,49 103.2,51.8 104.6,54.4 106.6,56.6 109.1,58.2 112,59.1 114.9,59.3 117.8,58.7 120.5,57.5 122.8,55.6 124.5,53.2 125.6,50.4
  Board Outline Layer region: 126,47.5 125.6,44.6 124.5,41.8 122.8,39.4 120.5,37.5 117.8,36.3 114.9,35.7 112,35.9 109.1,36.8 106.6,38.4 104.6,40.6 103.2,43.1 102.5,46 102.5,49 103.2,51.8 104.6,54.4 106.6,56.6 109.1,58.2 112,59.1 114.9,59.3 117.8,58.7 120.5,57.5 122.8,55.6 124.5,53.2 125.6,50.4
  Multi-Layer board cut-out: -102.4,47.5 -102.7,44.6 -103.8,41.8 -105.6,39.4 -107.8,37.5 -110.5,36.3 -113.4,35.7 -116.4,35.9 -119.2,36.8 -121.7,38.4 -123.7,40.6 -125.2,43.1 -125.9,46 -125.9,49 -125.2,51.8 -123.7,54.4 -121.7,56.6 -119.2,58.2 -116.4,59.1 -113.4,59.3 -110.5,58.7 -107.8,57.5 -105.6,55.6 -103.8,53.2 -102.7,50.4
  Multi-Layer board cut-out: 126,47.5 125.6,44.6 124.5,41.8 122.8,39.4 120.5,37.5 117.8,36.3 114.9,35.7 112,35.9 109.1,36.8 106.6,38.4 104.6,40.6 103.2,43.1 102.5,46 102.5,49 103.2,51.8 104.6,54.4 106.6,56.6 109.1,58.2 112,59.1 114.9,59.3 117.8,58.7 120.5,57.5 122.8,55.6 124.5,53.2 125.6,50.4
  silkscreen extent -176,-200 176,11

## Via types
v1: diameter 24, hole 12, Top Layer to Bottom Layer, 160 vias

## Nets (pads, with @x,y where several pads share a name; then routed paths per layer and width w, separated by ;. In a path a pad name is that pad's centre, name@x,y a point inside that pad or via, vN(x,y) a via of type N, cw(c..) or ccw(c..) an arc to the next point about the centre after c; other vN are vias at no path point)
$1N357: CN2.3 R3.1 U1.77 U2.20 U3.3 U4.4 U5.11 | length 4229.5
  Top Layer w7.8: U3.3@3921.3,3502.1 3921.3,3551.8 3906.7,3566.4 3906.7,3577.4 3931.2,3601.9 3958.9,3601.9 v1(3978.2,3621.3) ; U5.11@4364.3,4715.7 4364.3,4695.7 4379.4,4680.6 v1(4439.8,4680.6) ; U1.77@4400,4024.6 4400,3873.8 4450.8,3823 ; v1(4431.2,3803.4) 4450.8,3823 ; 4451.2,3823.4 4450.8,3823 ; v1(4537.6,4557.3) 4537.6,4557 4781.2,4313.4 4781.2,4080.9 4801.2,4060.9 4801.2,3853.4 4771.2,3823.4 v1(4741.2,3823.4) ; v1(4579.5,3694.4) 4450.8,3823
  Top Layer w8.9: U2.20@3809.6,3737.4 3931.2,3615.8 3931.2,3601.9
  Top Layer w10: R3.1@3725.8,3411.5 3761,3376.3 v1(3769.5,3376.3) ; CN2.3@4681.2,3666 4681.2,3724.3 v1(4691.6,3734.7) ; v1(4857.2,3651) 4877.7,3671.5 4921.2,3671.5 4929.2,3663.4 U4.4@4929.2,3628.5
  Bottom Layer w7.8: v1(3978.2,3621.3) 4039.1,3621.3 4091.2,3673.4 4311.2,3673.4 4431.2,3793.4 v1(4431.2,3803.4) ; v1(4439.8,4680.6) 4439.8,4600.2 4482.6,4557.3 v1(4537.6,4557.3) ; v1(4579.5,3694.4) 4618.5,3733.4 v1@4691.2,3733.4 ; v1(4691.6,3734.7) 4691.6,3733.9 v1@4691.2,3733.4 ; v1(4741.2,3823.4) 4691.2,3823.4 v1@4691.2,3733.4
  Bottom Layer w10: v1(3769.5,3376.3) 3804.7,3411.5 4072.4,3411.5 4122.4,3361.5 4279.6,3361.5 4579.5,3661.4 v1(4579.5,3694.4) ; v1(4691.6,3734.7) 4773.5,3734.7 v1(4857.2,3651)
$1N359: CN2.4 R4.1 U1.78 U2.19 U3.4 U4.5 U5.1 | length 3169
  Top Layer w7.8: U5.1@4408.5,4720.6 4412.8,4724.9 4422.5,4724.9 4428.3,4730.7 4428.3,4740.3 4432.9,4745 v1(4476.2,4745) ; v1(4455.5,4102.7) 4455.5,4079.9 4416.2,4040.7 4416.2,3894.5 4641.8,3668.9 CN2.4@4641.8,3666 ; v1(4584.8,4720.6) 4645.8,4659.6 4645.8,4531.6 v1(4635.8,4521.6)
  Top Layer w8.9: U2.19@3777.6,3737.4 3789,3726 v1(3789,3691.8) ; v1(3939,3576) 3959,3556
  Top Layer w10: U3.4@3952.8,3502.1 3959,3508.2 3959,3556 3959,3558.4 v1(3990.3,3589.8) ; R4.1@4316.7,3605.1 4316.7,3578.1 ccw(c4337.8,3578.1) v1@4322.88,3563.18 ; v1@4328.8,3559.7 4349.6,3580.5 4424.9,3580.5 4494.9,3510.5 4609.1,3510.5 4659.1,3560.5 4661.8,3560.5 ; CN2.4@4641.8,3666 4641.8,3640.5 4661.8,3620.5 4661.8,3560.5 ; v1@4691.5,3513.8 4674.2,3513.8 4661.8,3526.2 4661.8,3560.5 ; v1@4826.5,3512.7 ccw(c4826.5,3543.9) 4848.56,3521.84 ; 4848.5,3521.9 4869.2,3542.5 4869.2,3560.2 cw(c4969.2,3560.2) 4898.49,3630.91 U4.5@4909.9,3642.3
  Bottom Layer w7.8: 4437.9,4137.8 4437.9,4158.2 ; 4437.9,4161.5 4437.9,4172.8 cw(c4460.1,4172.8) 4444.4,4188.5 ; 4437.96,4158.26 cw(c4459.8,4159.9) 4437.96,4161.54 ; 4440.2,4137.8 4443.6,4134.3 4443.6,4121.4 ; 4443.7,4121.4 ccw(c4447.4,4121.4) 4444.78,4118.78 ; 4444.4,4116.7 4455.5,4105.6 v1(4455.5,4102.7) ; 4444.4,4189.4 4463.5,4208.5 4463.5,4349.3 v1(4635.8,4521.6) ; v1(4476.2,4745) 4500.6,4720.6 v1(4584.8,4720.6)
  Bottom Layer w8.9: v1(3789,3691.8) 3904.8,3576 v1(3939,3576)
  Bottom Layer w10: v1(3990.3,3589.8) 4037.7,3589.8 4099,3651 4234.4,3651 v1(4325.7,3559.7) ; v1@4696.4,3515.7 4808.3,3515.7 cw(c4808.3,3497.1) v1@4821.45,3510.25
  other v1: 4826,3509.3 4694.9,3513.3
$1N360: R9.1 U2.11 | length 1335.8
  Top Layer w8.9: U2.11@3686.6,3816.1 3700.8,3816.1 3770.8,3886.1 v1(3780.8,3886.1) ; v1(4555.3,4243.4) 4570,4243.4 4579.5,4252.9 4581.9,4252.9 4594.9,4265.9 R9.1@4604.3,4265.9
  Bottom Layer w8.9: v1(3780.8,3886.1) 3835.7,3940.9 3900.5,3876.1 4480.8,3876.1 4541.9,3937.1 4541.9,4187.1 4562.8,4208 4562.8,4211.3 4563.3,4211.9 4563.3,4230.5 4555.3,4238.5 v1(4555.3,4243.4)
$1N368: R5.2 R6.1 U15.4 | length 1985.9
  Top Layer w10: R6.1@3752.9,4036.2 3779.9,4009.1 v1(3779.9,3989.1) ; v1(4479.9,3914.4) 4489.9,3904.4 4569.9,3904.4 ; R5.2@4534.2,3864.3 4534.2,3868.7 4569.9,3904.4 ; v1(4619.2,3998.7) 4619.2,3936.2 4587.3,3904.4 4569.9,3904.4 ; v1(5035.4,4607.5) 5058.5,4584.4 U15.4@5129.9,4584.4
  Bottom Layer w10: v1(3779.9,3989.1) 3805.2,4014.4 3969.9,4014.4 4089.9,3894.4 4459.9,3894.4 v1(4479.9,3914.4) ; v1(4619.2,3998.7) 5035.4,4415 v1(5035.4,4607.5)
$1N370: C6.2 L2.1 U15.2 | length 1995.2
  Top Layer w10: L2.1@3723.1,4754.8 v1(3849.7,4754.8) ; v1(3979.7,4754.8) 4079.7,4854.8 4199.7,4854.8 v1(4219.7,4834.8) ; v1(4259.7,4874.8) 4309.7,4924.8 4399.7,4924.8 4439.7,4884.8 4439.7,4824.8 4506.2,4758.3 4506.2,4709.9 4455.4,4659.1 ; C6.2@4397.4,4639.1 4435.4,4639.1 4455.4,4659.1 ; v1(4508.5,4698.7) 4476.4,4666.5 4476.4,4640 4475.9,4639.6 4475,4639.6 4455.4,4659.1 ; v1(4704,4757.3) 4710.3,4751 5027.3,4751 5057.3,4721 5137.3,4721 5167.3,4691 U15.2@5167.3,4674.9
  Bottom Layer w10: v1(3849.7,4754.8) v1(3979.7,4754.8) ; v1(4219.7,4834.8) v1(4259.7,4874.8) ; v1(4508.5,4698.7) 4515.5,4705.7 4567.2,4705.7 4575.3,4697.6 4594.3,4697.6 4654,4757.3 v1(4704,4757.3)
$1N371: C6.1 U15.6 | length 1029.2
  Top Layer w10: C6.1@4364.3,4639.1 4364.3,4630.9 4384.7,4610.5 4480.5,4610.5 4480.6,4610.4 ; 4480.53,4610.4 ccw(c4491.4,4612.1) 4489.7,4601.23 ; 4489.7,4601.2 4489.7,4592.7 v1(4503.2,4579.2) ; v1(5164.7,4630.5) 5184.7,4630.5 5204.7,4610.5 U15.6@5204.7,4584.4
  Bottom Layer w10: v1(4503.2,4579.2) 4503.2,4612 4484.7,4630.5 4774.7,4630.5 4824.7,4580.5 4884.7,4580.5 4934.7,4630.5 v1(5164.7,4630.5)
$1N373: D2.2 USBC1.A4B9 USBC1.B4A9 | length 1777.9
  Top Layer w10: v1(3850.8,4099.9) 3916.9,4166 3916.9,4340.7 3889.5,4368 3889.5,4389.9 3883.2,4396.2 3883.2,4407 3861.8,4428.4 D2.2@3861.8,4541.9 ; v1(4140.8,3479.9) 4150.8,3469.9 4150.8,3419.9 ; USBC1.A4B9@4141.8,3359.3 4141.8,3410.9 4150.8,3419.9 ; USBC1.B4A9@4330.8,3359.3 4330.8,3399.9 4300.8,3429.9 4180.8,3429.9 4170.8,3419.9 4150.8,3419.9
  Bottom Layer w10: v1(3850.8,4099.9) 3720.8,3969.9 3720.8,3849.9 3759.4,3811.3 3759.4,3788.1 3987.6,3559.9 4110.9,3559.9 4140.8,3530 v1(4140.8,3479.9)
$1N378: L1.1 U1.63 | length 439.6
  Top Layer w7.8: L1.1@3833.8,4213 3834.6,4212.2 v1(3892.2,4212.2) ; v1(4149.6,4081.6) 4179.6,4051.6 U1.63@4179.6,4024.6
  Bottom Layer w7.8: v1(3892.2,4212.2) 4018.9,4212.2 v1(4149.6,4081.6)
$1N379: C17.1 C19.1 C20.1 L1.2 U1.10 U1.32 U1.51 U1.65 | length 2612.1
  Top Layer w7.8: C17.1@3816.6,4373.6 3847.4,4373.6 v1(3868.2,4352.7) ; L1.2@3833.8,4292.4 3846.2,4279.9 v1(3885.3,4279.9) ; v1(3913.5,4380.5) 3913.5,4369.5 3935.7,4347.3 3935.7,4163.8 3926.6,4154.6 3926.6,3993.6 v1(3916.6,3983.6) ; v1(4011.9,3918.5) 4022.6,3907.9 4022.6,3645.8 C19.1@4027.6,3640.7 ; U1.51@4104.5,4209.9 4130,4209.9 v1(4150,4189.9) ; U1.65@4211.1,4024.6 4211.1,4045.3 4187.9,4068.5 4187.9,4092 4180,4099.9 4180,4139.9 v1(4190,4149.9) 4190,4159.9 4220.8,4190.8 4220.8,4282.2 ; 4220.4,4284.2 4220.8,4284.2 4220.8,4284.7 cw(c4230.7,4284.7) 4230.7,4294.6 ; 4233.5,4295.6 4287.8,4295.6 ccw(c4287.8,4323.5) 4307.53,4303.77 ; U1.32@4274.1,4411 4274.1,4394 4259.6,4379.5 4259.6,4368.5 4284.1,4344 4294.1,4344 4307.5,4357.5 ; 4306.56,4360.26 cw(c4304.3,4358) 4307.5,4358 4307.5,4357.5 ; 4307.5,4303.8 4307.5,4357.5 ; C20.1@4475.2,4511.9 4488.5,4498.5 4488.5,4497.1 4525.1,4460.6 v1(4525.1,4449.1) ; U1.10@4490.9,4209.9 4471.4,4209.9 4467.3,4214 4467.3,4254 v1(4357.3,4364) 4314.1,4364 4307.5,4357.5
  Top Layer w10: C17.1@3816.6,4373.6 3833.8,4356.4 L1.2@3833.8,4292.4
  Bottom Layer w7.8: v1(3868.2,4352.7) 3896,4380.5 v1(3913.5,4380.5) ; v1(3885.3,4279.9) 3895.3,4289.9 4050,4289.9 v1(4150,4189.9) v1(4190,4149.9) ; v1(3916.6,3983.6) 3946.8,3983.6 v1(4011.9,3918.5) ; v1(4357.3,4364) 4405.2,4364 4424.3,4383.1 4459.2,4383.1 v1(4525.1,4449.1)
$1N380: C3.1 C4.1 C5.1 C7.1 R2.1 U1.61 | length 3256.4
  Top Layer w7.8: C7.1@3975.8,4094.7 3989.1,4081.4 3989.1,4080 3994.9,4074.2 3996.3,4074.2 3997,4073.5 v1(3997,4054.6) ; v1(4058.1,4044.6) 4078.1,4024.6 U1.61@4148.1,4024.6 4093.1,3969.6 v1(4093.1,3833.3) ; v1(4148.4,3791.7) 4148.4,3767.1 C3.1@4181.2,3734.4 ; v1(4181.2,3474.4) 4191.2,3464.4 4291.2,3464.4 4305.3,3450.3 v1(4471.6,3450.3) ; v1(4537,3567.6) 4537,3682.9 v1(4538.5,3684.4) ; C4.1@4591.9,4446.4 4621.3,4417 v1(4644.8,4417)
  Top Layer w10: R2.1@4032.6,3498.2 4032.6,3545.8 v1(4071.2,3584.4) ; v1(4104.1,3623.6) 4181.2,3700.7 C3.1@4181.2,3734.4 ; v1(4841.2,4114.4) 4841.2,3983.8 C5.1@5039.5,3785.6
  Bottom Layer w7.8: v1(3997,4054.6) 4007.1,4044.6 v1(4058.1,4044.6) ; v1(4071.2,3584.4) 4107.5,3584.4 4181.2,3510.7 v1(4181.2,3474.4) ; v1(4093.1,3833.3) 4106.8,3833.3 v1(4148.4,3791.7) ; v1(4471.6,3450.3) 4537,3515.7 v1(4537,3567.6) ; v1(4538.5,3684.4) 4603,3748.8 4603,3944.4 4603,3952.6 4581.2,3974.4 4581.2,4097.7 4675.7,4192.2 4675.7,4248.6 4644.8,4279.5 4644.8,4337.7 4626,4356.6 4626,4374.7 4644.8,4393.6 v1(4644.8,4417)
  Bottom Layer w10: v1(4071.2,3584.4) 4071.2,3590.7 v1(4104.1,3623.6) ; 4591.2,3944.4 4603,3944.4 4611.2,3944.4 4801.2,4134.4 4821.2,4134.4 v1(4841.2,4114.4)
$1N384: C2.1 U1.31 U12.2 | length 1504.8
  Top Layer w7.8: U12.2@3911.5,3746.2 3945.8,3711.9 v1(3945.8,3682.4) ; v1(4277.4,3757.1) 4277.4,3832.1 4346.6,3901.3 v1(4346.6,3933.5) ; U1.31@4289.8,4411 4289.8,4430.7 4309,4449.8 v1(4376,4449.8) ; C2.1@4370.3,4546.8 4370.3,4517.4 v1(4389.8,4498)
  Top Layer w10: v1(4312.3,4082.6) 4315.8,4086.1 4328.1,4086.1 ; 4328.14,4086.13 cw(c4307.3,4034.8) v1@4358.63,4055.64
  Bottom Layer w7.8: v1(3945.8,3682.4) 3953.9,3690.6 3953.9,3714.1 3982,3742.2 4005.6,3742.2 4011.3,3748 4268.3,3748 v1(4277.4,3757.1) ; 4311.6,4260.9 4335.6,4284.9 ccw(c4332.8,4306.6) 4335.62,4328.32 ; v1(4312.3,4082.6) 4312.3,4158.6 4313.5,4159.7 4313.5,4260.9 ; 4335.5,4409.4 v1(4376,4449.8) 4389.8,4463.7 v1(4389.8,4498) ; 4336.8,3946 ccw(c4336.8,3948.2) 4338.36,3946.64 ; 4338,4406.9 4345.2,4399.7 ; 4338.3,3946.6 4358.6,3966.9 v1(4358.6,4055.7) ; 4345.27,4399.77 cw(c4327.8,4382.3) 4352.31,4385.35 ; 4352.22,4385.3 ccw(c4357.3,4364) 4352.41,4342.65 ; 4352.5,4321 4352.5,4342.6
$1N387: R7.2 USBC1.A6 | length 509.5
  Top Layer w10: USBC1.A6@4226.5,3359.3 v1(4226.5,3399.9) ; R7.2@4349.2,3813.1 4354.7,3807.6 4354.7,3768.9 4355.1,3768.5 v1(4355.1,3669.9)
  Bottom Layer w10: v1(4226.5,3399.9) 4355.1,3528.5 v1(4355.1,3669.9)
$1N388: R8.2 USBC1.A8 | length 748.3
  Top Layer w10: USBC1.A8@4285.5,3359.3 v1(4285.5,3399.9) ; R8.2@4526.6,3959.4 4556,3930 v1(4573,3930)
  Bottom Layer w10: v1(4285.5,3399.9) 4515.5,3629.9 4515.5,3819.9 4573,3877.5 v1(4573,3930)
$1N391: R7.1 U1.67 | length 362.8
  Top Layer w7.8: v1(4233.1,3847.1) 4233.1,3913.2 4222.6,3923.8 4222.6,3981.6 4242.6,4001.6 U1.67@4242.6,4024.6 ; v1(4337.5,3853.7) 4357.3,3833.8 4367.6,3833.8 4383.3,3818.1 R7.1@4383.3,3813.1
  Bottom Layer w7.8: v1(4233.1,3847.1) 4330.9,3847.1 v1(4337.5,3853.7)
$1N392: U1.79 U8.1 | length 1547.6
  Top Layer w7.8: U1.79@4431.5,4024.6 4430,4023 4430,3911.7 v1(4488,3853.7)
  Bottom Layer w7.8: U8.1@3507.8,3474.5 4114.6,3474.5 4211.5,3377.6 4241.5,3377.6 4251.5,3387.6 4251.5,3397.6 4461.5,3607.6 4461.5,3827.2 v1(4488,3853.7)
$1N393: U1.80 U9.1 | length 1476.5
  Top Layer w7.8: U1.80@4447.3,4024.6 4471.3,4024.6 v1(4497.1,3998.8)
  Bottom Layer w7.8: U9.1@3256,4222.1 3296.5,4181.6 3827.3,4181.6 4097.3,3911.6 4427.3,3911.6 4487.3,3971.6 4487.3,3988.9 v1(4497.1,3998.8)
$1N394: U1.1 U10.1 | length 1443
  Top Layer w7.8: v1(3727.9,4268.2) 3747.9,4248.2 v1(3893.9,4248.2) ; v1(4211.3,4128.8) 4223.5,4140.9 4364.6,4140.9 ccw(c4364.6,4150.8) 4374.5,4150.8 4374.5,4204.9 4401.2,4231.6 v1(4438.1,4231.6) ; v1(4462.3,4052.4) 4475.1,4052.4 U1.1@4490.9,4068.2
  Bottom Layer w7.8: U10.1@3457.5,4446.6 3635.9,4268.2 v1(3727.9,4268.2) ; v1(3893.9,4248.2) 3913.9,4268.2 4037.9,4268.2 4177.2,4128.8 4180.1,4128.8 4180.9,4128 4199,4128 4199.9,4128.8 v1(4211.3,4128.8) ; 4423.62,4192.15 ccw(c4402.6,4198.3) 4423.62,4204.45 ; 4423.6,4192.2 4423.6,4106.3 ccw(c4429.1,4106.3) 4425.21,4102.41 ; 4423.6,4204.5 4423.6,4217.2 ; 4424.5,4218.1 v1(4438.1,4231.6) ; 4425.2,4102 4443.5,4083.7 4443.5,4066 4451.3,4058.2 4456.6,4058.2 v1(4462.3,4052.4)
$1N395: U1.2 U11.1 | length 3439.3
  Top Layer w10: U1.2@4500.2,4083.6 4541.5,4083.6 cw(c4541.5,4064.3) 4556.2,4051.79 ; 4557.9,4050 4598.7,4009.2 ; 4598.74,4009.21 cw(c4619.2,3998.7) 4639.66,3988.19 cw(c4619.2,3998.7) 4635.21,3982.18 ; 4635.1,3982.2 ccw(c4657.9,3982.2) 4641.78,3966.08 4682.8,3925.2 ; 4682.79,3925.09 cw(c4677.7,3920) 4684.9,3920 4684.9,3917 ccw(c4695.9,3917) 4689.93,3907.76 ; 4689.9,3907.8 4689.9,3798.7 v1@4715,3773.7 ; v1@4790.6,3766 4893.2,3766 cw(c4893.2,3666) 4963.91,3736.71 v1@4971.8,3728.8
  Bottom Layer w10: U11.1@3258.1,3954.7 3258.1,3795.1 ccw(c3358.1,3795.1) 3287.39,3724.39 3315.2,3696.6 ; 3315.17,3696.52 cw(c3296.2,3622.1) 3370.62,3641.07 ; 3370.7,3641.1 3384.6,3627.2 3384.6,3549.9 ccw(c3484.6,3549.9) 3413.89,3479.19 3656.1,3237 3974.8,3237 ; 3957.4,3233.6 4454.6,3233.6 ; 4454.2,3234 4454.6,3233.6 ; v1@4718.3,3771.7 4761.8,3771.7 cw(c4761.8,3730.9) v1@4790.65,3759.75 ; v1@4970.3,3727.2 4970.3,3720.6 ccw(c5070.3,3720.6) 4999.59,3649.89 ; 5000.8,3649.5 5091.3,3559 ; 5091.36,3558.96 cw(c5077.5,3545.1) 5097.1,3545.1 ; 5098,3545.1 5098,3514.6 ccw(c5098,3414.6) 5027.29,3485.31 4775.6,3233.6 4454.6,3233.6
  other v1: 4973.2,3729.1 4788.5,3760.4 4716.5,3770.9
$1N398: H1.3 H2.3 U1.34 | length 1754.4
  Top Layer w7.8: v1(4199.8,4451.8) 4217.6,4434 4235.2,4434 4241,4428.2 4241,4412.5 U1.34@4242.6,4411
  Bottom Layer w7.8: H2.3@4124.8,4907.4 4172.6,4859.6 4172.6,4611 4262.6,4521 4262.6,4514.5 4260.2,4512.2 4260.2,4475 4244.8,4459.6 4207.6,4459.6 v1(4199.8,4451.8)
  Bottom Layer w10: 3614.1,5088.8 3608.7,5083.4 3608.7,5043.4 3638.7,5013.4 3704.3,5013.4 H1.3@3754.3,5063.4 ; 3614.11,5088.86 cw(c3655.2,5078) 3644.34,5119.09 ; 3644.4,5119.1 3676,5150.7 4058.8,5150.7 4105.8,5103.7 4109.5,5103.7 ; 4110.3,5104.2 4110.3,5033 4016.8,4939.4 4086.8,4869.4 H2.3@4124.8,4907.4
$1N399: H1.4 H2.1 U1.33 | length 819.7
  Top Layer w7.8: v1(4238.3,4492.5) 4258.3,4472.5 U1.33@4258.3,4411
  Bottom Layer w7.8: H2.1@4124.8,4707.4 4124.8,4606.1 v1(4238.3,4492.5)
  Bottom Layer w10: H1.4@3854.3,5063.4 3984.8,4932.9 3984.8,4886.9 4124.8,4746.9 H2.1@4124.8,4707.4
$1N400: H1.7 U1.46 | length 1285.7
  Top Layer w7.8: v1@3900.2,5060.2 3914,5073.9 ; 3914,5073.96 cw(c3955.2,5078) 3959.24,5119.2 ; v1(3952.4,4932.7) 3952.4,4969.7 v1(3970.5,4987.7) ; 3959.3,5119.2 3960.2,5120.1 ccw(c3943.7,5136.6) 3966.91,5134.61 ; 3967,5134.6 4083.1,5134.6 H1.7@4154.3,5063.4 ; 3967.71,5130.81 ccw(c3944.5,5132.8) 3967.8,5132.8 ; U1.46@4104.5,4288.6 4120.1,4288.6 4126.9,4281.9 v1(4147.4,4281.9)
  Bottom Layer w7.8: v1(3903.9,5059.9) 3903.9,5054.4 v1(3970.5,4987.7) ; v1(3952.4,4932.7) 3952.4,4898.2 4042.6,4808 4042.6,4357.2 4054.3,4345.5 4070.7,4345.5 4134.2,4281.9 v1(4147.4,4281.9)
$1N401: H1.8 U1.45 | length 1121.2
  Top Layer w7.8: U1.45@4104.5,4304.4 4127.5,4304.4 v1(4137.5,4314.4)
  Bottom Layer w7.8: v1(4137.5,4314.4) v1@4139,4314.4 ; H1.8@4254.3,5063.4 4315.4,5124.6 4375.3,5124.6 4404.3,5095.6 4404.3,5053.4 4374.3,5023.4 4374.3,4553
  Bottom Layer w10: v1@4142.5,4314.5 4176.4,4348.4 ; 4176.36,4348.5 ccw(c4179.4,4371.3) 4202.2,4374.34 ; 4202.2,4374.3 4371.7,4543.8 ccw(c4362.5,4553) 4375.5,4553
